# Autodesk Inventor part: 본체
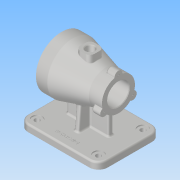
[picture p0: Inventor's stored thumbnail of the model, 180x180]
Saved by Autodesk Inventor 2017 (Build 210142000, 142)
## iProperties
Part Number: 본체
Material: 알루미늄 6061
Document SubType Name: Modeling
Designer: user
Density: 2.7 g/cm^3
Appearance: 알루미늄 - 평지
Mass: 1223.12 g
Surface Area: 899.626 cm^2
Volume: 453.008 cm^3
Author: user
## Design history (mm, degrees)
sketch "스케치3"
  geometry: L1 (70, 55)-(-70, 55); L2 (-70, 55)-(-70, -55); L3 (-70, -55)-(70, -55); L4 (70, -55)-(70, 55); L5 (70, 55)-(-70, -55); L6 (-70, 55)-(70, -55); 1 further point
  constraints: 12 end point, 2 midpoint, 2 parallel, 1 horizontal, 1 perpendicular
  dimensions: "d0" = 140 distance of L3.end L2.end; "d1" = 110 distance of L2.end L1.end
extrude "돌출1" new body sketch "스케치3" distance "d2" = 12; taper "d3" = 0 deg
sketch "스케치4"
  geometry: L1 (-50, 127)-(-30, 127); L2 (-30, 127)-(27, 111); L3 (27, 111)-(50, 111); L4 (50, 111)-(50, 82); L5 (50, 82)-(-50, 82); L6 (-50, 82)-(-50, 127); 2 further points
  constraints: 12 end point, 3 perpendicular, 1 horizontal, 1 midpoint, 1 parallel, 1 vertical alignment
  dimensions: "d4" = 82 distance from line of L5 point (0, 0); "d5" = 100 distance of L4.end L5.end; "d6" = 20 distance of L1.start L1.end; "d7" = 23 distance of L2.end L3.end; "d8" = 90 diameter of L1 L5; "d9" = 58 diameter of L3 L5; "d89" = 50 horizontal distance of point (0, 82) L1.start (derived)
revolve "회전1" sketch "스케치4" stored, may be unused: angle "d10" = 90 deg
sketch "스케치5"
  geometry: L1 (-37, -4)-(37, -4); L2 (37, -4)-(37, 4); L3 (37, 4)-(-37, 4); L4 (-37, 4)-(-37, -4); L5 (-37, -4)-(37, 4); L6 (37, -4)-(-37, 4); L7 (-4, -24)-(4, -24); L8 (4, -24)-(4, 24); L9 (4, 24)-(-4, 24); L10 (-4, 24)-(-4, -24); L11 (-4, -24)-(4, 24); L12 (4, -24)-(-4, 24); 1 further point
  constraints: 24 end point, 4 midpoint, 4 parallel, 2 horizontal, 2 perpendicular
  dimensions: "d11" = 74 distance of L3.end L2.end; "d12" = 8 distance of L2.end L1.end; "d13" = 8 distance of L9.end L8.end; "d14" = 48 distance of L8.end L7.end; "d90" = 24 distance from line of L7 point (0, 0) (derived); "d91" = 24 distance from line of L9 point (0, 0) (derived)
extrude "돌출2" join sketch "스케치5" stored distance "d15" = 12; taper "d16" = 0 deg
feature "면 기울기1" dims angle "d17" = 5 deg
feature "면 기울기2" dims angle "d18" = 5 deg
node "작업 평면1"
sketch "스케치6"
  geometry: L1 (12.5, 12.5)-(-12.5, 12.5); L2 (-12.5, 12.5)-(-12.5, -12.5); L3 (-12.5, -12.5)-(12.5, -12.5); L4 (12.5, -12.5)-(12.5, 12.5); L5 (12.5, 12.5)-(-12.5, -12.5); L6 (-12.5, 12.5)-(12.5, -12.5); 1 further point
  constraints: 12 end point, 2 midpoint, 2 parallel, 1 horizontal, 1 perpendicular
  dimensions: "d20" = 25 distance of L3.end L2.end; "d21" = 25 distance of L2.end L1.end
extrude "돌출3" join sketch "스케치6" stored distance "d22" = 10; taper "d23" = 0 deg
sketch "스케치7"
  geometry: L1 (0, 0)-(0, 29); L2 (0, 0)-(-25.115, -14.5); L3 (0, 0)-(25.115, -14.5); C1 r 7 at (0, 29); C2 r 7 at (-25.115, -14.5); C3 r 7 at (25.115, -14.5); A1 r 29 centre (0, 0) between (0, 29) and (-25.115, -14.5) reference; 2 further points
  constraints: 6 end point, 3 centre point, 3 coincident, 3 point on circle, 1 vertical
  dimensions: "d25" = 120 deg angle of L2 L1; "d26" = 120 deg angle of L3 L1; "d28" = 14 diameter of C1; "d29" = 14 diameter of C2; "d30" = 14 diameter of C3
extrude "돌출4" join sketch "스케치7" distance "d31" = 15; taper "d32" = 0 deg
sketch "스케치8"
  geometry: A1 r 7 centre (0, 0) between (6.949, -0.845) and (-6.949, -0.845) reference; A2 r 7 centre (-25.115, -43.5) between (-27.858, -37.06) and (-20.909, -49.095) reference; A3 r 7 centre (25.115, -43.5) between (20.909, -49.095) and (27.858, -37.06) reference; 4 further points
  constraints: 3 coincident
hole "구멍1" sketch "스케치8" at (0, 0), (25.115, -43.5), (-25.115, -43.5) diameter "d33" = 3.242; stored, may be unused: countersink angle "d37" = 90 deg, drill point angle "d39" = 118 deg; dims "d34" = 9, "d35" = 4, "d36" = 2, "d38" = 11
sketch "스케치9"
  geometry: L1 (-50, 37)-(-50, 127) reference; L2 (-50, 82)-(50, 82); L3 (-50, 82)-(-50, 113); L4 (-50, 113)-(-30, 113); L5 (-27, 110)-(-27, 110); L6 (-24, 107)-(17, 107); L7 (20, 104)-(20, 104); L8 (23, 101)-(50, 101); L9 (50, 101)-(50, 82); A1 r 3 centre (-30, 110) between (-27, 110) and (-30, 113); A2 r 3 centre (-24, 110) between (-27, 110) and (-24, 107); A3 r 3 centre (17, 104) between (20, 104) and (17, 107); A4 r 3 centre (23, 104) between (20, 104) and (23, 101); 5 further points
  constraints: 16 end point, 9 point on line, 8 point on circle, 8 tangent, 5 perpendicular, 4 centre point, 3 equal radius, 2 horizontal, 1 midpoint
  dimensions: "d40" = 100 distance of L2.start L2.end; "d41" = 23 distance of L3.end point (-27, 113); "d42" = 30 distance of point (20, 101) L8.end; "d43" = 47 distance of point (-27, 107) point (20, 107) (derived); "d44" = 62 diameter of L4 L2; "d45" = 50 diameter of L6 L2; "d46" = 38 diameter of L8 L2; "d47" = 3 radius of A1
revolve "회전2" sketch "스케치9" stored, may be unused: angle "d48" = 90 deg
sketch "스케치10"
  geometry: C1 r 7.5 at (0, 0); 1 further point
  constraints: 1 centre point, 1 coincident
  dimensions: "d49" = 15 diameter of C1
extrude "돌출5" cut sketch "스케치10" distance "d50" = 50; taper "d51" = 0 deg
sketch "스케치11"
  geometry: L1 (0, 0)-(0, 40); L2 (0, 0)-(-34.641, 20); L3 (0, 0)-(-34.641, -20); L4 (0, 0)-(0, -40); L5 (0, 0)-(34.641, -20); L6 (0, 0)-(34.641, 20); C1 r 45 at (0, 0) reference; A1 r 40 centre (0, 0) between (0, 40) and (-34.641, 20); 7 further points
  constraints: 12 end point, 7 coincident, 6 point on circle, 2 vertical, 1 centre point, 1 point on line
  dimensions: "d52" = 80 diameter of A1; "d53" = 60 deg angle of L2 L1; "d54" = 60 deg angle of L3 L2; "d55" = 60 deg angle of L5 L4
hole "구멍2" sketch "스케치11" at (0, 40), (-34.641, 20), (-34.641, -20), (0, -40), (34.641, -20), (34.641, 20) diameter "d56" = 3.242; stored, may be unused: countersink angle "d60" = 90 deg, drill point angle "d62" = 118 deg; dims "d57" = 9, "d58" = 4, "d59" = 2, "d61" = 11
fillet "모깎기1" dims "d63" = 16
sketch "스케치12"
  geometry: C1 r 9 at (-54, 39); C2 r 9 at (54, 39); C3 r 9 at (54, -39); C4 r 9 at (-54, -39); A1 r 16 centre (54, 39) between (70, 39) and (54, 55) reference; A2 r 16 centre (-54, 39) between (-54, 55) and (-70, 39) reference; A3 r 16 centre (-54, -39) between (-70, -39) and (-54, -55) reference; A4 r 16 centre (54, -39) between (54, -55) and (70, -39) reference; 1 further point
  constraints: 4 centre point, 4 coincident
  dimensions: "d64" = 18 diameter of C1; "d65" = 18 diameter of C2; "d66" = 18 diameter of C3; "d67" = 18 diameter of C4
extrude "돌출6" cut sketch "스케치12" distance "d68" = 2; taper "d69" = 0 deg
sketch "스케치13"
  geometry: C1 r 4.5 at (-54, 39); C2 r 4.5 at (54, 39); C3 r 4.5 at (54, -39); C4 r 4.5 at (-54, -39); A1 r 16 centre (54, 39) between (70, 39) and (54, 55) reference; A2 r 16 centre (-54, 39) between (-54, 55) and (-70, 39) reference; A3 r 16 centre (-54, -39) between (-70, -39) and (-54, -55) reference; A4 r 16 centre (54, -39) between (54, -55) and (70, -39) reference; 1 further point
  constraints: 4 centre point, 4 coincident
  dimensions: "d70" = 9 diameter of C1; "d71" = 9 diameter of C2; "d72" = 9 diameter of C3; "d73" = 9 diameter of C4
extrude "돌출7" cut sketch "스케치13" stored distance "d74" = 10; taper "d75" = 0 deg
chamfer "모따기1" distance "d76" = 1; stored, may be unused: second distance "d77" = 2, angle "d78" = 45 deg
fillet "모깎기2" dims "d79" = 8
fillet "모깎기3" dims "d80" = 1
fillet "모깎기4" dims "d81" = 3
fillet "모깎기5" dims "d82" = 3
fillet "모깎기6" dims "d83" = 3
fillet "모깎기7" dims "d84" = 1
node "작업 평면2"
sketch "스케치15"
  geometry: L1 (54, 55)-(-54, 55) reference; 2 further points
  constraints: 1 other
  dimensions: "d92" = 15 distance from line of point (0, 40) L1
feature "엠보싱1" sketch "스케치15" dims "d0" = 140, "d1" = 110, "d11" = 74, "d12" = 8, "d86" = 0.5, "d87" = 0
fillet "모깎기8" dims "d88" = 3
node "솔리드1"
other parameters: "d19" = 127, "d85" = 13
